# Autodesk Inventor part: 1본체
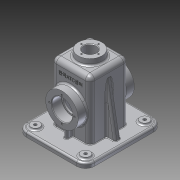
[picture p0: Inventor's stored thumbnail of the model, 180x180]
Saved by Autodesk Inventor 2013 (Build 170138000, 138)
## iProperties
Created: 2016-01
Part Number: 1본체
Material: 알루미늄 6061
Document SubType Name: Modeling
Designer: Administrator
Density: 2.71 g/cm^3
Mass: 807.487 g
Surface Area: 908.682 cm^2
Volume: 297.966 cm^3
Author: Administrator
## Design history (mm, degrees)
sketch "스케치1"
  geometry: L1 (-32.5, 32.5)-(32.5, 32.5); L2 (32.5, 32.5)-(32.5, -32.5); L3 (32.5, -32.5)-(-32.5, -32.5); L4 (-32.5, -32.5)-(-32.5, 32.5); 3 further points
  constraints: 8 end point, 2 midpoint, 2 parallel, 1 horizontal, 1 horizontal alignment, 1 perpendicular, 1 vertical alignment
  dimensions: "d0" = 65 distance of L2.end L3.end; "d1" = 65 distance of L1.end L2.end
extrude "돌출1" new body sketch "스케치1" distance "d2" = 110; taper "d3" = 0 deg
fillet "모깎기1" dims "d4" = 8
fillet "모깎기2" dims "d5" = 8
feature "쉘1" dims "d6" = 5
node "작업 평면1"
sketch "스케치2"
  geometry: C1 r 20 at (0, 0); 1 further point
  constraints: 1 centre point, 1 coincident
  dimensions: "d8" = 40 diameter of C1
extrude "돌출2" join sketch "스케치2" stored distance "d9" = 110; taper "d10" = 5 deg
sketch "스케치3"
  geometry: C1 r 20 at (0, 0) reference; C2 r 10.5 at (0, 0)
  constraints: 1 centre point, 1 coincident
  dimensions: "d11" = 21 diameter of C2
extrude "돌출3" cut sketch "스케치3" stored distance "d12" = 110; taper "d13" = 0 deg
chamfer "모따기1" distance "d14" = 1; stored, may be unused: second distance "d15" = 2, angle "d16" = 45 deg
sketch "스케치4" dims "d17" = 29
  geometry: L1 (0, 0)-(0, -14.5); C1 r 11.5 at (0, 0) reference; 1 further point
  constraints: 2 coincident, 2 end point, 1 vertical, 1 vertical alignment, 2 other
hole "구멍1" sketch "스케치4" at (0, -14.5) diameter "d18" = 2.459; stored, may be unused: countersink angle "d22" = 90 deg, drill point angle "d24" = 118 deg; dims "d19" = 7, "d20" = 4, "d21" = 2, "d23" = 9
sketch "스케치5"
  geometry: L1 (49, 0)-(0, 0) reference; C1 r 27.5 at (24.5, 55); 2 further points
  constraints: 1 centre point, 1 midpoint, 1 vertical alignment
  dimensions: "d28" = 55 diameter of C1; "d29" = 55 distance of point (24.5, 0) C1.centre
extrude "돌출4" join sketch "스케치5" distance "d30" = 15; taper "d32" = 0 deg; dims "d31" = 3, "d33" = 0
sketch "스케치6"
  geometry: C1 r 27.5 at (0, 0) reference; 2 further points
  constraints: 1 coincident
hole "구멍2" sketch "스케치6" at (0, 0) diameter "d35" = 35; stored, may be unused: countersink angle "d39" = 90 deg, drill point angle "d41" = 0 deg; dims "d36" = 7, "d37" = 4, "d38" = 2, "d40" = 17
sketch "스케치7"
  geometry: C1 r 17.5 at (0, 0) reference; 2 further points
  constraints: 1 coincident
hole "구멍3" sketch "스케치7" at (0, 0) diameter "d42" = 30; stored, may be unused: countersink angle "d46" = 90 deg, drill point angle "d48" = 0 deg; dims "d43" = 7, "d44" = 4, "d45" = 2, "d47" = 17
fillet "모깎기4" dims "d49" = 3
fillet "모깎기5" dims "d50" = 0.3
sketch "스케치9" dims "d51" = 42
  geometry: L1 (0, 0)-(0, -21); C1 r 27.5 at (0, 0) reference; 2 further points
  constraints: 2 coincident, 2 end point, 1 vertical, 1 vertical alignment, 2 other
hole "구멍4" sketch "스케치9" at (0, -21) diameter "d52" = 3.242; stored, may be unused: countersink angle "d56" = 90 deg, drill point angle "d58" = 118 deg; dims "d53" = 8, "d54" = 4, "d55" = 2, "d57" = 10
sketch "스케치10"
  geometry: L1 (24.5, 32.5)-(-24.5, 32.5) reference; L2 (-32.5, 24.5)-(-32.5, -24.5) reference; L3 (-24.5, -32.5)-(24.5, -32.5) reference; L4 (32.5, -24.5)-(32.5, 24.5) reference; L5 (-52.5, -60)-(52.5, -60); L6 (52.5, -60)-(52.5, 60); L7 (52.5, 60)-(-52.5, 60); L8 (-52.5, 60)-(-52.5, -60); A1 r 8 centre (24.5, 24.5) between (32.5, 24.5) and (24.5, 32.5) reference; A2 r 8 centre (-24.5, 24.5) between (-24.5, 32.5) and (-32.5, 24.5) reference; A3 r 8 centre (-24.5, -24.5) between (-32.5, -24.5) and (-24.5, -32.5) reference; A4 r 8 centre (24.5, -24.5) between (24.5, -32.5) and (32.5, -24.5) reference; 3 further points
  constraints: 8 end point, 2 midpoint, 2 parallel, 1 horizontal, 1 horizontal alignment, 1 perpendicular, 1 vertical alignment
  dimensions: "d62" = 105 distance of L7.end L6.end; "d63" = 120 distance of L6.end L5.end
extrude "돌출5" join sketch "스케치10" distance "d64" = 2; taper "d65" = 0 deg
fillet "모깎기6" dims "d66" = 10
sketch "스케치11"
  geometry: L1 (24.5, 32.5)-(-24.5, 32.5) reference; L2 (32.5, -24.5)-(32.5, 24.5) reference; L3 (-24.5, -32.5)-(24.5, -32.5) reference; L4 (-32.5, 24.5)-(-32.5, -24.5) reference; L5 (57.5, -65)-(-57.5, -65); L6 (-57.5, -65)-(-57.5, 65); L7 (-57.5, 65)-(57.5, 65); L8 (57.5, 65)-(57.5, -65); A1 r 8 centre (24.5, 24.5) between (32.5, 24.5) and (24.5, 32.5) reference; A2 r 8 centre (24.5, -24.5) between (24.5, -32.5) and (32.5, -24.5) reference; A3 r 8 centre (-24.5, -24.5) between (-32.5, -24.5) and (-24.5, -32.5) reference; A4 r 8 centre (-24.5, 24.5) between (-24.5, 32.5) and (-32.5, 24.5) reference; 3 further points
  constraints: 8 end point, 2 midpoint, 2 parallel, 1 horizontal, 1 horizontal alignment, 1 perpendicular, 1 vertical alignment
  dimensions: "d67" = 115 distance of L6.end L7.end; "d68" = 130 distance of L5.end L6.end
extrude "돌출6" join sketch "스케치11" distance "d69" = 8; taper "d70" = 0 deg
fillet "모깎기7" dims "d71" = 15
sketch "스케치12"
  geometry: L1 (42.5, 50)-(-42.5, 50); L2 (-42.5, 50)-(-42.5, -50); L3 (-42.5, -50)-(42.5, -50); L4 (42.5, -50)-(42.5, 50); C1 r 7.5 at (-42.5, 50); C2 r 7.5 at (42.5, 50); C3 r 7.5 at (42.5, -50); C4 r 7.5 at (-42.5, -50); 3 further points
  constraints: 8 end point, 4 centre point, 3 coincident, 2 midpoint, 2 parallel, 1 horizontal, 1 horizontal alignment, 1 perpendicular, 1 vertical alignment
  dimensions: "d72" = 85 distance of L3.end L2.end; "d73" = 100 distance of L2.end L1.end; "d74" = 15 diameter of C1; "d75" = 15 diameter of C2; "d76" = 15 diameter of C3; "d77" = 15 diameter of C4
extrude "돌출7" join sketch "스케치12" distance "d78" = 3; taper "d79" = 0 deg
hole "구멍5" diameter "d82" = 5; stored, may be unused: countersink angle "d86" = 90 deg, drill point angle "d88" = 0 deg; dims "d80" = 10, "d81" = 10, "d83" = 8, "d84" = 4, "d85" = 2, "d87" = 10
hole "구멍6" diameter "d91" = 5; stored, may be unused: countersink angle "d95" = 90 deg, drill point angle "d97" = 0 deg; dims "d89" = 10, "d90" = 10, "d92" = 8, "d93" = 4, "d94" = 2, "d96" = 10
hole "구멍7" diameter "d100" = 5; stored, may be unused: countersink angle "d104" = 90 deg, drill point angle "d106" = 0 deg; dims "d98" = 10, "d99" = 10, "d101" = 8, "d102" = 4, "d103" = 2, "d105" = 10
hole "구멍8" diameter "d109" = 5; stored, may be unused: countersink angle "d113" = 90 deg, drill point angle "d115" = 0 deg; dims "d107" = 10, "d108" = 10, "d110" = 8, "d111" = 4, "d112" = 2, "d114" = 10
fillet "모깎기8" dims "d116" = 3
fillet "모깎기9" dims "d117" = 3
node "작업 평면3"
sketch "스케치13"
  geometry: L1 (35, 17)-(36, 18) reference; L2 (36, 18)-(37.771, 18) reference; L3 (37.771, 18)-(37.771, 9) reference; L4 (37.771, 9)-(39, 8.261) reference; L5 (39, 8.261)-(40.23, 9) reference; L6 (40.23, 9)-(40.23, 18) reference; L7 (40.23, 18)-(44.5, 18) reference; L8 (44.5, 18)-(45.375, 8) reference; L9 (45.375, 8)-(49, 8) reference; L10 (57, 0)-(57, -92) reference; L11 (57, -92)-(79, -92) reference; L12 (82, -95)-(82, -100) reference; L13 (82, -100)-(77, -100) reference; L14 (77, -100)-(77, -102) reference; L15 (77, -102)-(52, -102) reference; L16 (52, -102)-(52, 0) reference; L17 (49, 3)-(35, 3) reference; L18 (35, 3)-(35, 17) reference; L19 (0, 8)-(3.625, 8) reference; L20 (3.625, 8)-(4.5, 18) reference; L21 (4.5, 18)-(8.771, 18) reference; L22 (8.771, 18)-(8.771, 9) reference; L23 (8.771, 9)-(10, 8.261) reference; L24 (10, 8.261)-(11.23, 9) reference; L25 (11.23, 9)-(11.23, 18) reference; L26 (11.23, 18)-(13, 18) reference; L27 (13, 18)-(14, 17) reference; L28 (14, 17)-(14, 3) reference; L29 (14, 3)-(0, 3) reference; L30 (-3, 0)-(-3, -102) reference; L31 (-3, -102)-(-28, -102) reference; L32 (-28, -102)-(-28, -100) reference; L33 (-28, -100)-(-33, -100) reference; L34 (-33, -100)-(-33, -95) reference; L35 (-30, -92)-(-8, -92) reference; L36 (-8, -92)-(-8, 0) reference; L37 (-8, -6.931)-(-23, -92); A1 r 8 centre (49, 0) between (57, 0) and (49, 8) reference; A2 r 3 centre (79, -95) between (82, -95) and (79, -92) reference; A3 r 3 centre (49, 0) between (52, 0) and (49, 3) reference; A4 r 8 centre (0, 0) between (0, 8) and (-8, 0) reference; A5 r 3 centre (0, 0) between (0, 3) and (-3, 0) reference; A6 r 3 centre (-30, -95) between (-30, -92) and (-33, -95) reference; 1 further point
  constraints: 2 end point, 2 point on line
  dimensions: "d118" = 10 horizontal distance of L37.end L34.end; "d119" = 10 deg angle of L34 L37
feature "리브1" sketch "스케치13" dims "d120" = 1, "d121" = 10, "d122" = 0, "d123" = 0, "d124" = 1, "d125" = 1
node "작업 평면4"
sketch "스케치14"
  geometry: L1 (64.5, 55.3)-(64.5, 72) reference; L2 (64.5, 72)-(66.379, 72) reference; L3 (66.379, 72)-(66.379, 62) reference; L4 (66.379, 62)-(68, 61.026) reference; L5 (68, 61.026)-(69.621, 62) reference; L6 (69.621, 62)-(69.621, 72) reference; L7 (69.621, 72)-(74.5, 72) reference; L8 (74.5, 72)-(74.5, 60) reference; L9 (77.5, 57)-(92, 57) reference; L10 (92, 57)-(92, 86.5) reference; L11 (95, 89.5)-(100, 89.5) reference; L12 (100, 89.5)-(100, 84.5) reference; L13 (100, 84.5)-(102, 84.5) reference; L14 (102, 84.5)-(102, 52) reference; L15 (102, 52)-(62, 52) reference; L16 (62, 52)-(62, 55) reference; L17 (62, 55)-(64.2, 55) reference; L18 (64.2, -6)-(62, -6) reference; L19 (62, -6)-(62, -3) reference; L20 (62, -3)-(102, -3) reference; L21 (102, -3)-(102, -35.5) reference; L22 (102, -35.5)-(100, -35.5) reference; L23 (100, -35.5)-(100, -40.5) reference; L24 (100, -40.5)-(95, -40.5) reference; L25 (92, -37.5)-(92, -8) reference; L26 (92, -8)-(77.5, -8) reference; L27 (74.5, -11)-(74.5, -23) reference; L28 (74.5, -23)-(69.621, -23) reference; L29 (69.621, -23)-(69.621, -13) reference; L30 (69.621, -13)-(68, -12.026) reference; L31 (68, -12.026)-(66.379, -13) reference; L32 (66.379, -13)-(66.379, -23) reference; L33 (66.379, -23)-(64.5, -23) reference; L34 (64.5, -23)-(64.5, -6.3) reference; L35 (-9, 37.771)-(-8.261, 39) reference; L36 (-8.261, 39)-(-9, 40.23) reference; L37 (-9, 40.23)-(-18, 40.23) reference; L38 (-18, 40.23)-(-18, 44.5) reference; L39 (-18, 44.5)-(-8, 45.375) reference; L40 (-8, 45.375)-(-8, 49) reference; L41 (0, 57)-(16.5, 57) reference; L42 (19.5, 60)-(19.5, 72) reference; L43 (19.5, 72)-(24.379, 72) reference; L44 (24.379, 72)-(24.379, 62) reference; L45 (24.379, 62)-(26, 61.026) reference; L46 (26, 61.026)-(27.621, 62) reference; L47 (27.621, 62)-(27.621, 72) reference; L48 (27.621, 72)-(29.5, 72) reference; L49 (29.5, 72)-(29.5, 55.3) reference; L50 (29.8, 55)-(32, 55) reference; L51 (32, 55)-(32, 52) reference; L52 (32, 52)-(0, 52) reference; L53 (-3, 49)-(-3, 35) reference; L54 (-3, 35)-(-17, 35) reference; L55 (-17, 35)-(-18, 36) reference; L56 (-18, 36)-(-18, 37.771) reference; L57 (-18, 37.771)-(-9, 37.771) reference; L58 (-8.261, 10)-(-9, 11.229) reference; L59 (-9, 11.229)-(-18, 11.229) reference; L60 (-18, 11.229)-(-18, 13) reference; L61 (-18, 13)-(-17, 14) reference; L62 (-17, 14)-(-3, 14) reference; L63 (-3, 14)-(-3, 0) reference; L64 (0, -3)-(32, -3) reference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; A1 r 0.3 centre (64.2, 55.3) between (64.2, 55) and (64.5, 55.3) reference; A2 r 3 centre (77.5, 60) between (74.5, 60) and (77.5, 57) reference; A3 r 3 centre (95, 86.5) between (95, 89.5) and (92, 86.5) reference; A4 r 0.3 centre (64.2, -6.3) between (64.5, -6.3) and (64.2, -6) reference; A5 r 3 centre (95, -37.5) between (92, -37.5) and (95, -40.5) reference; A6 r 3 centre (77.5, -11) between (77.5, -8) and (74.5, -11) reference; A7 r 8 centre (0, 49) between (0, 57) and (-8, 49) reference; A8 r 3 centre (16.5, 60) between (16.5, 57) and (19.5, 60) reference; A9 r 0.3 centre (29.8, 55.3) between (29.5, 55.3) and (29.8, 55) reference; A10 r 3 centre (0, 49) between (0, 52) and (-3, 49) reference; A11 r 3 centre (0, 0) between (-3, 0) and (0, -3) reference; A12 r 0.3 centre (29.8, -6.3) between (29.8, -6) and (29.5, -6.3) reference; A13 r 3 centre (16.5, -11) between (19.5, -11) and (16.5, -8) reference; A14 r 8 centre (0, 0) between (-8, 0) and (0, -8) reference; 1 further point
  constraints: 2 end point, 2 point on line, 1 horizontal
  dimensions: "d126" = 15 distance between parallel lines of L20 L82
feature "리브2" sketch "스케치14" dims "d127" = 1, "d128" = 6, "d129" = 0, "d130" = 0, "d131" = 1, "d132" = 1
fillet "모깎기10" dims "d133" = 3
fillet "모깎기11" dims "d134" = 3
chamfer "모따기2" distance "d136" = 1; stored, may be unused: second distance "d137" = 2, angle "d138" = 45 deg
sketch "스케치15"
  geometry: L1 (4.5, 18)-(44.5, 18) reference; L2 (-8, 0)-(-8, -92) reference; A1 r 30.5 centre (24.5, -47) between (49, -28.834) and (0, -28.834) reference; 3 further points
  constraints: 1 vertical alignment, 1 other
  dimensions: "d139" = 27 distance from line of L1 point (24.5, -9); "d140" = 32.5 distance from line of point (24.5, -9) L2 (derived)
feature "엠보싱1" sketch "스케치15" dims "d6" = 5, "d141" = 0.5, "d142" = 0
fillet "모깎기13" dims "d143" = 3
fillet "모깎기14" dims "d144" = 1
node "솔리드1"
pattern_circular "원형 패턴1" dims angle "d26" = 360 deg
mirror "대칭1"
pattern_circular "원형 패턴2" dims angle "d60" = 360 deg
mirror "대칭2"
mirror "대칭3"
mirror "대칭4"
node "절단 모서리 투영2"
node "절단 모서리 투영3"
